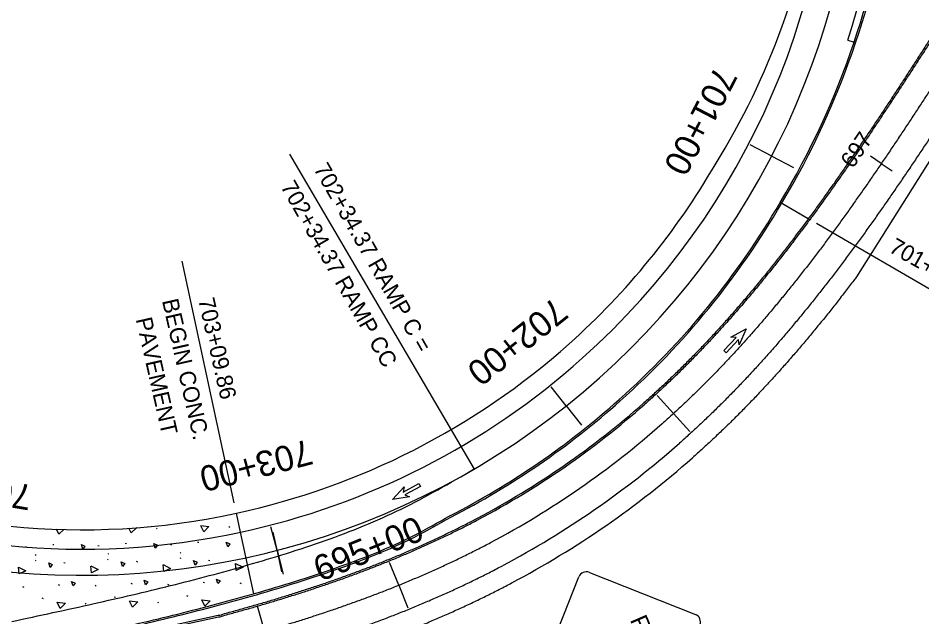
# Model space of a CAD drawing. Extents: x 0 to 1360, y 0 to 880.
# Drawn here: x 409.3 to 686.9, y 130.5 to 314.3 of the extents above; entities that cross this region are included whole.
import ezdxf

# ---------------------------------------------------------------- set-up
doc = ezdxf.new("R2010")
doc.units = 0
for name, color, linetype in [('Default', 7, 'Continuous'), ('PM_P_Cells', 7, 'Continuous'), ('PV_X_Curb', 7, 'Continuous'), ('PV_X_EOP', 7, 'Continuous'), ('PV_X_Shoulder', 7, 'Continuous'), ('RD_X_Concrete_Pad', 7, 'Continuous'), ('SH_Text', 7, 'Continuous'), ('SN_P_Signs', 7, 'Continuous')]:
    doc.layers.add(name, color=color, linetype=linetype)

# ---------------------------------------------------------------- blocks, each defined once
blk = doc.blocks.new('PMTHRP')
at = {"layer": 'PM_P_Cells'}
for p, q in [((-9.5, -0.5), (-9.5, 0.5)), ((-9.5, 0.5), (-4, 0.5)), ((-9.5, 0), (-9.5, 0)), ((-4, 0.5), (-5, 1.74)), ((-5, 1.74), (0, 0)), ((0, 0), (-5, -1.74)), ((0, 0), (0, 0)), ((-4, -0.5), (-9.5, -0.5)), ((-5, -1.74), (-4, -0.5))]:
    blk.add_line(p, q, dxfattribs=at)

msp = doc.modelspace()

# ---------------------------------------------------------------- linework, layer by layer
at = {"layer": 'Default'}
for p, q in [((640.76, 271.88), (634.11, 275.34)), ((492.7, 272.46), (549.36, 175.87)), ((640.76, 271.88), (647.41, 268.42)), ((674.4, 269.6), (671.09, 271.85)), ((674.4, 269.6), (677.71, 267.34)), ((652, 252.65), (643.35, 257.66)), ((742.46, 200.18), (654.51, 251.19)), ((475.67, 165.53), (459.67, 239.64)), ((577.66, 195.25), (572.98, 201.12)), ((610.59, 192.9), (605.53, 198.44)), ((577.66, 195.25), (582.33, 189.38)), ((610.59, 192.9), (615.64, 187.36)), ((429.7, 157.28), (429.55, 157.17)), ((452.05, 157.72), (451.78, 157.53)), ((474.29, 158.08), (474.02, 157.9)), ((488.84, 150.91), (486.96, 158.17)), ((489.28, 149.21), (487.69, 156.54)), ((442.57, 153), (442.17, 152.95)), ((455.99, 152.81), (456.39, 152.63)), ((464.81, 153.36), (464.41, 153.31)), ((478.23, 153.17), (478.35, 153.12)), ((411.52, 152.08), (411.92, 151.91)), ((420.33, 152.64), (419.94, 152.58)), ((433.75, 152.44), (434.16, 152.27)), ((459.32, 150.24), (459.06, 150.06)), ((488.84, 150.91), (490.72, 143.65)), ((414.77, 147.84), (414.51, 147.65)), ((414.85, 149.52), (414.59, 149.33)), ((423.36, 147.22), (423.76, 147.05)), ((437.01, 148.2), (436.75, 148.02)), ((437.09, 149.88), (436.82, 149.7)), ((445.6, 147.58), (446, 147.41)), ((459.25, 148.56), (458.99, 148.38)), ((467.83, 147.95), (468.24, 147.77)), ((490.33, 144.33), (489.28, 149.21)), ((526.22, 140.23), (523.4, 147.18)), ((410.69, 139.82), (411.1, 139.65)), ((421.65, 140.44), (422.05, 140.27)), ((432.93, 140.18), (433.33, 140.01)), ((443.89, 140.81), (444.29, 140.63)), ((455.17, 140.55), (455.57, 140.37)), ((466.12, 141.17), (466.53, 141)), ((477.41, 140.91), (477.81, 140.74)), ((526.22, 140.23), (529.04, 133.28)), ((416.56, 136.32), (416.97, 136.15)), ((438.8, 136.68), (439.2, 136.51)), ((461.04, 137.04), (461.44, 136.87)), ((430.18, 134.59), (429.92, 134.41)), ((452.42, 134.95), (452.15, 134.77))]:
    msp.add_line(p, q, dxfattribs=at)
for points in [[(465.38, 158.52), (467.92, 158.21), (466.31, 156.6), (465.4, 158.48)], [(423.31, 157.35), (421.83, 155.87), (421.09, 157.41)], [(445.44, 157.88), (445.69, 157.85), (444.07, 156.24), (443.35, 157.74)], [(450.97, 153.03), (452.09, 152.52), (451.44, 151.62), (450.97, 153.03)], [(473.21, 153.4), (474.33, 152.88), (473.67, 151.98), (473.21, 153.4)], [(428.73, 152.67), (429.85, 152.16), (429.2, 151.26), (428.73, 152.67)], [(440.94, 147.42), (442.05, 146.9), (441.4, 146), (440.94, 147.42)], [(463.17, 147.78), (464.29, 147.27), (463.64, 146.37), (463.17, 147.78)], [(409.4, 145.79), (411.68, 144.63), (409.61, 143.67), (409.4, 145.75)], [(418.7, 147.06), (419.82, 146.54), (419.17, 145.64), (418.7, 147.06)], [(431.64, 146.16), (433.92, 144.99), (431.85, 144.03), (431.64, 146.11)], [(453.87, 146.52), (456.16, 145.36), (454.09, 144.39), (453.87, 146.47)], [(476.11, 146.88), (478.39, 145.72), (476.32, 144.75), (476.11, 146.84)], [(447.98, 141.75), (449.1, 141.24), (448.45, 140.34), (447.98, 141.75)], [(470.22, 142.11), (471.34, 141.6), (470.68, 140.7), (470.22, 142.11)], [(425.74, 141.39), (426.86, 140.87), (426.21, 139.98), (425.74, 141.39)], [(421.28, 135.03), (423.82, 134.72), (422.2, 133.11), (421.29, 134.99)], [(443.51, 135.4), (446.06, 135.09), (444.44, 133.47), (443.53, 135.36)], [(465.75, 135.76), (468.3, 135.45), (466.68, 133.83), (465.77, 135.72)]]:
    msp.add_lwpolyline(points, dxfattribs=at)
for centre, radius, start, end in [((428.95, 382.01), 238.73, 311.7475, 51.7475), ((429.97, 386.9), 249.78, 341.2739, 353.787), ((430.58, 385.7), 248.32, 328.9635, 341.4934), ((430.58, 385.7), 248.82, 328.9635, 341.4934), ((428.95, 382.01), 230.73, 211.5995, 282.1946), ((428.95, 382.01), 238.73, 211.5995, 311.7475), ((429.19, 382.3), 247.79, 311.6606, 329.8014), ((429.19, 382.3), 248.29, 311.6606, 329.8014), ((428.85, 382.13), 247.89, 297.144, 311.7439), ((428.85, 382.13), 248.39, 297.144, 311.7439), ((426.57, 394.35), 264.34, 297.9333, 311.4333), ((426.57, 394.35), 264.84, 297.9333, 311.4333), ((426.57, 394.35), 272.84, 297.9333, 311.4333), ((426.57, 394.35), 280.84, 297.9333, 311.4333)]:
    msp.add_arc(centre, radius, start, end, dxfattribs=at)
for points in [[(692.15, 312.1), (691.05, 310.4), (689.95, 308.7), (688.85, 307), (687.76, 305.3), (686.66, 303.6), (685.56, 301.9), (684.46, 300.2), (683.36, 298.51), (682.26, 296.81), (681.16, 295.12), (680.06, 293.43), (678.95, 291.74), (677.84, 290.06), (676.74, 288.37), (675.63, 286.69), (674.52, 285.01), (673.4, 283.34), (672.28, 281.66), (671.17, 279.99), (670.04, 278.32), (668.92, 276.66), (667.79, 275), (666.66, 273.34), (665.53, 271.68), (664.39, 270.03), (663.25, 268.38), (662.1, 266.73), (660.96, 265.09), (659.8, 263.45), (658.64, 261.82), (657.48, 260.19), (656.32, 258.57), (655.15, 256.95), (653.97, 255.33), (652.79, 253.72), (652, 252.65)], [(699.29, 307.5), (698.19, 305.79), (697.09, 304.09), (696, 302.39), (694.9, 300.68), (693.8, 298.98), (692.69, 297.28), (691.59, 295.58), (690.49, 293.88), (689.38, 292.18), (688.28, 290.48), (687.17, 288.78), (686.06, 287.09), (684.95, 285.39), (683.83, 283.7), (682.72, 282.01), (681.6, 280.32), (680.48, 278.63), (679.35, 276.94), (678.22, 275.26), (677.09, 273.57), (675.96, 271.89), (674.82, 270.22), (673.68, 268.54), (672.54, 266.87), (671.39, 265.2), (670.23, 263.53), (669.07, 261.87), (667.91, 260.21), (666.74, 258.55), (665.57, 256.9), (664.4, 255.25), (663.21, 253.6), (662.03, 251.96), (660.83, 250.32), (659.64, 248.68), (658.43, 247.05), (657.22, 245.43), (656.01, 243.8), (654.78, 242.19), (653.55, 240.57), (652.32, 238.97), (651.08, 237.36), (649.83, 235.77), (648.58, 234.18), (647.31, 232.59), (646.04, 231.01), (644.77, 229.44), (643.48, 227.87), (642.19, 226.3), (640.89, 224.75), (639.58, 223.2), (638.27, 221.66), (636.95, 220.12), (635.62, 218.59), (634.28, 217.07), (632.93, 215.56), (631.57, 214.05), (630.21, 212.55), (628.83, 211.06), (627.45, 209.58), (626.06, 208.1), (624.66, 206.64), (623.25, 205.18), (621.83, 203.73), (620.4, 202.3), (618.97, 200.87), (617.52, 199.45), (616.06, 198.04), (614.6, 196.64), (613.12, 195.25), (611.64, 193.87), (610.14, 192.5), (608.64, 191.14), (607.12, 189.79)], [(652, 252.65), (651.6, 252.11), (650.41, 250.51), (649.21, 248.92), (648.01, 247.33), (646.8, 245.74), (645.59, 244.16), (644.37, 242.59), (643.14, 241.02), (641.91, 239.45), (640.67, 237.9), (639.43, 236.35), (638.18, 234.8), (636.92, 233.27), (635.65, 231.74), (634.38, 230.21), (633.1, 228.7), (631.82, 227.19), (630.52, 225.69), (629.22, 224.19), (627.91, 222.71), (626.6, 221.23), (625.27, 219.76), (623.94, 218.29), (622.6, 216.84), (621.25, 215.39), (619.9, 213.96), (618.53, 212.53), (617.16, 211.11), (615.78, 209.7), (614.39, 208.3), (612.99, 206.91), (611.59, 205.53), (610.17, 204.16), (608.75, 202.8), (607.32, 201.45), (605.87, 200.12), (604.42, 198.79), (602.97, 197.47), (601.47, 196.14)], [(652.43, 252.39), (652, 251.82), (650.81, 250.21), (649.61, 248.62), (648.41, 247.02), (647.2, 245.44), (645.99, 243.85), (644.77, 242.28), (643.54, 240.71), (642.3, 239.14), (641.06, 237.59), (639.82, 236.03), (638.56, 234.49), (637.3, 232.95), (636.04, 231.42), (634.76, 229.89), (633.48, 228.37), (632.2, 226.86), (630.9, 225.36), (629.6, 223.86), (628.29, 222.37), (626.97, 220.89), (625.64, 219.42), (624.31, 217.96), (622.97, 216.5), (621.62, 215.05), (620.26, 213.61), (618.89, 212.18), (617.52, 210.76), (616.14, 209.35), (614.74, 207.95), (613.34, 206.56), (611.94, 205.17), (610.52, 203.8), (609.09, 202.44), (607.66, 201.09), (606.21, 199.75), (604.76, 198.42), (603.3, 197.1), (601.81, 195.77)], [(407.38, 129.06), (432.62, 134.58), (456.13, 140.1), (479.83, 146.42), (503.62, 153.93), (526.94, 163.59), (549.22, 175.79)], [(470.73, 130.97), (470.75, 130.97), (472.68, 131.49), (474.61, 132.02), (476.54, 132.55), (478.46, 133.09), (480.38, 133.63), (482.3, 134.18), (484.22, 134.74), (486.13, 135.3), (488.04, 135.87), (489.95, 136.45), (491.85, 137.04), (493.75, 137.64), (495.65, 138.24), (497.54, 138.85), (499.43, 139.47), (501.31, 140.1), (503.2, 140.73), (505.07, 141.38), (506.95, 142.03), (508.82, 142.69), (510.68, 143.36), (512.55, 144.05), (514.4, 144.74), (516.26, 145.44), (518.1, 146.15), (519.95, 146.87), (521.78, 147.6), (523.62, 148.34), (525.44, 149.09), (527.27, 149.86), (529.08, 150.63), (530.89, 151.42), (532.7, 152.21), (534.5, 153.02), (536.29, 153.84), (538.08, 154.67), (539.86, 155.51), (541.63, 156.36), (543.4, 157.22), (545.16, 158.1), (546.92, 158.99), (548.66, 159.89), (550.43, 160.82)], [(470.86, 130.49), (470.88, 130.49), (472.81, 131.01), (474.74, 131.54), (476.67, 132.07), (478.6, 132.61), (480.52, 133.15), (482.44, 133.7), (484.36, 134.26), (486.27, 134.82), (488.19, 135.4), (490.09, 135.98), (492, 136.56), (493.9, 137.16), (495.8, 137.76), (497.69, 138.37), (499.59, 138.99), (501.47, 139.62), (503.36, 140.26), (505.24, 140.9), (507.11, 141.56), (508.99, 142.22), (510.86, 142.89), (512.72, 143.58), (514.58, 144.27), (516.43, 144.97), (518.28, 145.68), (520.13, 146.41), (521.97, 147.14), (523.81, 147.88), (525.64, 148.63), (527.46, 149.4), (529.28, 150.17), (531.09, 150.96), (532.9, 151.75), (534.7, 152.56), (536.5, 153.38), (538.29, 154.21), (540.07, 155.06), (541.85, 155.91), (543.62, 156.78), (545.39, 157.65), (547.14, 158.55), (548.89, 159.45), (550.66, 160.38)], [(411.75, 108.52), (413.73, 108.94), (415.71, 109.37), (417.69, 109.8), (419.67, 110.23), (421.66, 110.66), (423.64, 111.09), (425.62, 111.52), (427.6, 111.96), (429.58, 112.39), (431.56, 112.83), (433.54, 113.27), (435.51, 113.71), (437.49, 114.15), (439.47, 114.6), (441.45, 115.04), (443.42, 115.5), (445.4, 115.95), (447.37, 116.41), (449.35, 116.87), (451.32, 117.34), (453.29, 117.81), (455.26, 118.28), (457.23, 118.76), (459.2, 119.24), (461.17, 119.73), (463.13, 120.22), (465.1, 120.72), (467.06, 121.22), (469.02, 121.73), (470.99, 122.24), (472.94, 122.76), (474.9, 123.29), (476.86, 123.82), (478.81, 124.36), (480.76, 124.9), (482.71, 125.46), (484.66, 126.02), (486.61, 126.58), (488.55, 127.16), (490.5, 127.74), (492.43, 128.33), (494.37, 128.92), (496.31, 129.53), (498.24, 130.14), (500.17, 130.77), (502.09, 131.4), (504.02, 132.04), (505.94, 132.69), (507.85, 133.34), (509.77, 134.01), (511.68, 134.69), (513.59, 135.38), (515.49, 136.07), (517.39, 136.78), (519.29, 137.5), (521.18, 138.22), (523.06, 138.96), (524.95, 139.71), (526.83, 140.47), (528.7, 141.24), (530.57, 142.03), (532.44, 142.82), (534.3, 143.63), (536.15, 144.44), (538, 145.27), (539.85, 146.11), (541.68, 146.97), (543.52, 147.83), (545.34, 148.71), (547.16, 149.6), (548.98, 150.51), (550.79, 151.42), (552.59, 152.35), (554.38, 153.3)]]:
    msp.add_spline(points, degree=3, dxfattribs=at)
at = {"layer": 'PV_X_Curb'}
for p, q in [((652.43, 252.39), (643.35, 257.66)), ((244.24, 82.07), (470.75, 130.97)), ((244.34, 81.58), (470.86, 130.49)), ((294.88, 92.49), (470.86, 130.49))]:
    msp.add_line(p, q, dxfattribs=at)
for centre, radius, start, end in [((429.97, 386.9), 249.28, 341.2739, 352.7439), ((429.97, 386.9), 249.28, 341.2739, 352.7439), ((430.58, 385.7), 248.32, 328.9635, 341.4934), ((429.19, 382.3), 247.79, 311.6606, 329.8014), ((428.85, 382.13), 247.89, 297.144, 311.7439), ((426.57, 394.35), 264.84, 297.9333, 311.4333)]:
    msp.add_arc(centre, radius, start, end, dxfattribs=at)
for points in [[(652.43, 252.39), (652, 251.82), (650.81, 250.21), (649.61, 248.62), (648.41, 247.02), (647.2, 245.44), (645.99, 243.85), (644.77, 242.28), (643.54, 240.71), (642.3, 239.14), (641.06, 237.59), (639.82, 236.03), (638.56, 234.49), (637.3, 232.95), (636.04, 231.42), (634.76, 229.89), (633.48, 228.37), (632.2, 226.86), (630.9, 225.36), (629.6, 223.86), (628.29, 222.37), (626.97, 220.89), (625.64, 219.42), (624.31, 217.96), (622.97, 216.5), (621.62, 215.05), (620.26, 213.61), (618.89, 212.18), (617.52, 210.76), (616.14, 209.35), (614.74, 207.95), (613.34, 206.56), (611.94, 205.17), (610.52, 203.8), (609.09, 202.44), (607.66, 201.09), (606.21, 199.75), (604.76, 198.42), (603.3, 197.1), (601.81, 195.77)], [(409.3, 120.26), (434.61, 125.8), (458.32, 131.37), (482.34, 137.78), (506.71, 145.47), (530.83, 155.46), (541.98, 161.57)], [(409.3, 120.26), (434.61, 125.8), (458.32, 131.37), (482.34, 137.78), (506.71, 145.47), (530.83, 155.46), (541.98, 161.57)], [(409.41, 119.77), (434.72, 125.31), (458.44, 130.89), (482.48, 137.3), (506.88, 145), (531.05, 155.01), (542.22, 161.13)], [(470.86, 130.49), (470.88, 130.49), (472.81, 131.01), (474.74, 131.54), (476.67, 132.07), (478.6, 132.61), (480.52, 133.15), (482.44, 133.7), (484.36, 134.26), (486.27, 134.82), (488.19, 135.4), (490.09, 135.98), (492, 136.56), (493.9, 137.16), (495.8, 137.76), (497.69, 138.37), (499.59, 138.99), (501.47, 139.62), (503.36, 140.26), (505.24, 140.9), (507.11, 141.56), (508.99, 142.22), (510.86, 142.89), (512.72, 143.58), (514.58, 144.27), (516.43, 144.97), (518.28, 145.68), (520.13, 146.41), (521.97, 147.14), (523.81, 147.88), (525.64, 148.63), (527.46, 149.4), (529.28, 150.17), (531.09, 150.96), (532.9, 151.75), (534.7, 152.56), (536.5, 153.38), (538.29, 154.21), (540.07, 155.06), (541.85, 155.91), (543.62, 156.78), (545.39, 157.65), (547.14, 158.55), (548.89, 159.45), (550.66, 160.38)]]:
    msp.add_spline(points, degree=3, dxfattribs=at)
at = {"layer": 'PV_X_EOP'}
msp.add_line((664.15, 307.48), (666.06, 306.87), dxfattribs=at)
for radius, start, end in [(246.73, 342.4182, 51.7475), (230.73, 311.7475, 51.7475), (230.73, 282.1946, 311.7475)]:
    msp.add_arc((428.95, 382.01), radius, start, end, dxfattribs=at)
for points in [[(692.57, 311.83), (691.47, 310.13), (690.37, 308.43), (689.27, 306.72), (688.18, 305.02), (687.08, 303.33), (685.98, 301.63), (684.88, 299.93), (683.78, 298.23), (682.68, 296.54), (681.58, 294.85), (680.47, 293.16), (679.37, 291.47), (678.26, 289.78), (677.15, 288.1), (676.04, 286.42), (674.93, 284.74), (673.82, 283.06), (672.7, 281.38), (671.58, 279.71), (670.46, 278.04), (669.33, 276.38), (668.21, 274.71), (667.07, 273.05), (665.94, 271.4), (664.8, 269.74), (663.66, 268.09), (662.51, 266.45), (661.36, 264.8), (660.21, 263.17), (659.05, 261.53), (657.89, 259.9), (656.72, 258.28), (655.55, 256.65), (654.37, 255.04), (653.19, 253.42), (652.43, 252.39)], [(706.02, 303.16), (704.92, 301.46), (703.82, 299.75), (702.72, 298.05), (701.62, 296.34), (700.51, 294.64), (699.41, 292.93), (698.31, 291.23), (697.2, 289.52), (696.09, 287.81), (694.98, 286.11), (693.87, 284.41), (692.75, 282.7), (691.63, 281), (690.51, 279.3), (689.39, 277.59), (688.27, 275.89), (687.14, 274.19), (686, 272.5), (684.87, 270.8), (683.73, 269.1), (682.59, 267.41), (681.44, 265.72), (680.29, 264.03), (679.13, 262.34), (677.97, 260.65), (676.8, 258.97), (675.63, 257.29), (674.46, 255.61), (673.28, 253.94), (672.09, 252.26), (670.9, 250.59), (669.71, 248.92), (668.5, 247.26), (667.29, 245.6), (666.08, 243.94), (664.86, 242.29), (663.63, 240.64), (662.4, 238.99), (661.16, 237.35), (659.91, 235.71), (658.65, 234.08), (657.39, 232.45), (656.12, 230.83), (654.85, 229.21), (653.56, 227.59), (652.27, 225.99), (650.97, 224.38), (649.66, 222.78), (648.34, 221.19), (647.02, 219.61), (645.69, 218.03), (644.34, 216.45), (642.99, 214.88), (641.63, 213.32), (640.27, 211.77), (638.89, 210.22), (637.5, 208.68), (636.11, 207.15), (634.7, 205.62), (633.29, 204.11), (631.86, 202.6), (630.43, 201.09), (628.98, 199.6), (627.53, 198.12), (626.06, 196.64), (624.59, 195.18), (623.1, 193.72), (621.61, 192.27), (620.1, 190.83), (618.59, 189.4), (617.06, 187.99), (615.52, 186.58), (613.98, 185.18), (612.44, 183.81)], [(487.4, 118.48), (488.86, 118.9), (490.83, 119.49), (492.81, 120.08), (494.78, 120.68), (496.75, 121.28), (498.71, 121.9), (500.68, 122.52), (502.64, 123.16), (504.6, 123.8), (506.56, 124.45), (508.52, 125.11), (510.47, 125.78), (512.42, 126.46), (514.37, 127.15), (516.32, 127.86), (518.26, 128.57), (520.2, 129.29), (522.14, 130.02), (524.07, 130.77), (526, 131.52), (527.93, 132.29), (529.85, 133.07), (531.77, 133.85), (533.68, 134.66), (535.59, 135.47), (537.5, 136.3), (539.4, 137.13), (541.3, 137.98), (543.19, 138.85), (545.08, 139.72), (546.96, 140.61), (548.84, 141.51), (550.71, 142.43), (552.57, 143.36), (554.43, 144.3), (556.28, 145.26), (558.1, 146.21)]]:
    msp.add_spline(points, degree=3, dxfattribs=at)
at = {"layer": 'PV_X_Shoulder'}
msp.add_line((720.13, 319.51), (666.79, 234.85), dxfattribs=at)
msp.add_line((720.13, 319.51), (666.79, 234.85), dxfattribs=at)
for centre, radius, start, end in [((431.19, 388.86), 226.34, 328.1016, 352.1016), ((428.95, 382.01), 224.73, 311.7475, 329.8882), ((428.95, 382.01), 224.73, 282.1791, 311.7475), ((426.57, 394.35), 286.84, 297.9333, 311.4333), ((426.57, 394.35), 286.84, 297.9333, 311.4333)]:
    msp.add_arc(centre, radius, start, end, dxfattribs=at)
for points in [[(692.57, 311.83), (691.47, 310.13), (690.37, 308.43), (689.27, 306.72), (688.18, 305.02), (687.08, 303.33), (685.98, 301.63), (684.88, 299.93), (683.78, 298.23), (682.68, 296.54), (681.58, 294.85), (680.47, 293.16), (679.37, 291.47), (678.26, 289.78), (677.15, 288.1), (676.04, 286.42), (674.93, 284.74), (673.82, 283.06), (672.7, 281.38), (671.58, 279.71), (670.46, 278.04), (669.33, 276.38), (668.21, 274.71), (667.07, 273.05), (665.94, 271.4), (664.8, 269.74), (663.66, 268.09), (662.51, 266.45), (661.36, 264.8), (660.21, 263.17), (659.05, 261.53), (657.89, 259.9), (656.72, 258.28), (655.55, 256.65), (654.37, 255.04), (653.19, 253.42), (652.43, 252.39)], [(666.79, 234.85), (665.94, 233.72), (664.67, 232.07), (663.4, 230.42), (662.13, 228.77), (660.84, 227.12), (659.55, 225.48), (658.25, 223.85), (656.94, 222.22), (655.62, 220.59), (654.29, 218.97), (652.96, 217.36), (651.62, 215.75), (650.26, 214.14), (648.9, 212.55), (647.53, 210.96), (646.15, 209.37), (644.76, 207.79), (643.36, 206.22), (641.95, 204.65), (640.53, 203.09), (639.1, 201.54), (637.66, 200), (636.21, 198.46), (634.75, 196.94), (633.28, 195.42), (631.8, 193.9), (630.31, 192.4), (628.81, 190.91), (627.29, 189.42), (625.77, 187.95), (624.23, 186.48), (622.69, 185.02), (621.13, 183.58), (619.56, 182.14), (617.98, 180.71), (616.43, 179.33)], [(666.79, 234.85), (665.94, 233.72), (664.67, 232.07), (663.4, 230.42), (662.13, 228.77), (660.84, 227.12), (659.55, 225.48), (658.25, 223.85), (656.94, 222.22), (655.62, 220.59), (654.29, 218.97), (652.96, 217.36), (651.62, 215.75), (650.26, 214.14), (648.9, 212.55), (647.53, 210.96), (646.15, 209.37), (644.76, 207.79), (643.36, 206.22), (641.95, 204.65), (640.53, 203.09), (639.1, 201.54), (637.66, 200), (636.21, 198.46), (634.75, 196.94), (633.28, 195.42), (631.8, 193.9), (630.31, 192.4), (628.81, 190.91), (627.29, 189.42), (625.77, 187.95), (624.23, 186.48), (622.69, 185.02), (621.13, 183.58), (619.56, 182.14), (617.98, 180.71), (616.43, 179.33)], [(488.92, 112.67), (490.55, 113.15), (492.54, 113.74), (494.54, 114.33), (496.53, 114.94), (498.53, 115.55), (500.52, 116.18), (502.51, 116.81), (504.5, 117.45), (506.48, 118.1), (508.47, 118.76), (510.45, 119.43), (512.43, 120.11), (514.41, 120.8), (516.39, 121.5), (518.37, 122.22), (520.34, 122.94), (522.31, 123.67), (524.28, 124.42), (526.24, 125.17), (528.2, 125.94), (530.16, 126.72), (532.12, 127.51), (534.07, 128.31), (536.02, 129.13), (537.96, 129.96), (539.9, 130.8), (541.84, 131.65), (543.77, 132.52), (545.7, 133.4), (547.62, 134.29), (549.54, 135.2), (551.45, 136.12), (553.36, 137.05), (555.27, 138), (557.16, 138.96), (559.05, 139.94), (560.89, 140.9)]]:
    msp.add_spline(points, degree=3, dxfattribs=at)
at = {"layer": 'RD_X_Concrete_Pad'}
for p, q in [((477.62, 156.47), (476.36, 162.33)), ((481.7, 137.6), (477.62, 156.47)), ((488.92, 112.67), (482.8, 133.8))]:
    msp.add_line(p, q, dxfattribs=at)
msp.add_arc((428.98, 381.96), 224.73, 211.5995, 282.1741, dxfattribs=at)
at = {"layer": 'SN_P_Signs'}
for points in [[(568.64, 110.2), (581.51, 142.74)], [(584.76, 144.15), (617.3, 131.27)]]:
    msp.add_lwpolyline(points, dxfattribs=at)
for centre, start, end in [((583.84, 141.82), 68.4154, 158.4154), ((616.39, 128.95), 338.4154, 68.4154)]:
    msp.add_arc(centre, 2.5, start, end, dxfattribs=at)

# ---------------------------------------------------------------- block references
at = {"layer": 'SH_Text'}
for p, rotation in [((632.88, 218.85), 47.04069910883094), ((524.27, 166.49), -151.8204771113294)]:
    msp.add_blockref('PMTHRP', p, dxfattribs=dict(at, rotation=rotation))

# ---------------------------------------------------------------- texts
at = {"layer": 'Default'}
for s, height, rotation, p in [('701+00', 7.8, 242.5292, (623.57, 299.98)), ('697', 5, 55.7444, (665.68, 267.85)), ('702+34.37 RAMP C =', 5, 299.6287, (499.93, 268.03)), ('702+34.37 RAMP CC', 5, 299.6287, (489.78, 262.58)), ('701+11(C) = 696+74(D)', 5, 330.331, (676.42, 242.71)), ('BEGIN CONC.', 5, 282.717, (453.48, 227.55)), ('703+09.86', 5, 282.717, (464.59, 227.86)), ('702+00', 7.8, 218.5292, (574.01, 228.88)), ('PAVEMENT', 5, 282.717, (445.42, 221.86)), ('703+00', 7.8, 194.5292, (498.45, 185.08)), ('704+00', 7.8, 170.5292, (413.99, 170.83)), ('695+00', 7.8, 22.086, (502.06, 141.21))]:
    msp.add_text(s, height=height, rotation=rotation, dxfattribs=at).set_placement(p)
at = {"layer": 'SN_P_Signs'}
msp.add_text('ROAD', height=5.331, rotation=293.4154, dxfattribs=at).set_placement((597.14, 129.58))

doc.saveas('drawing.dxf')
